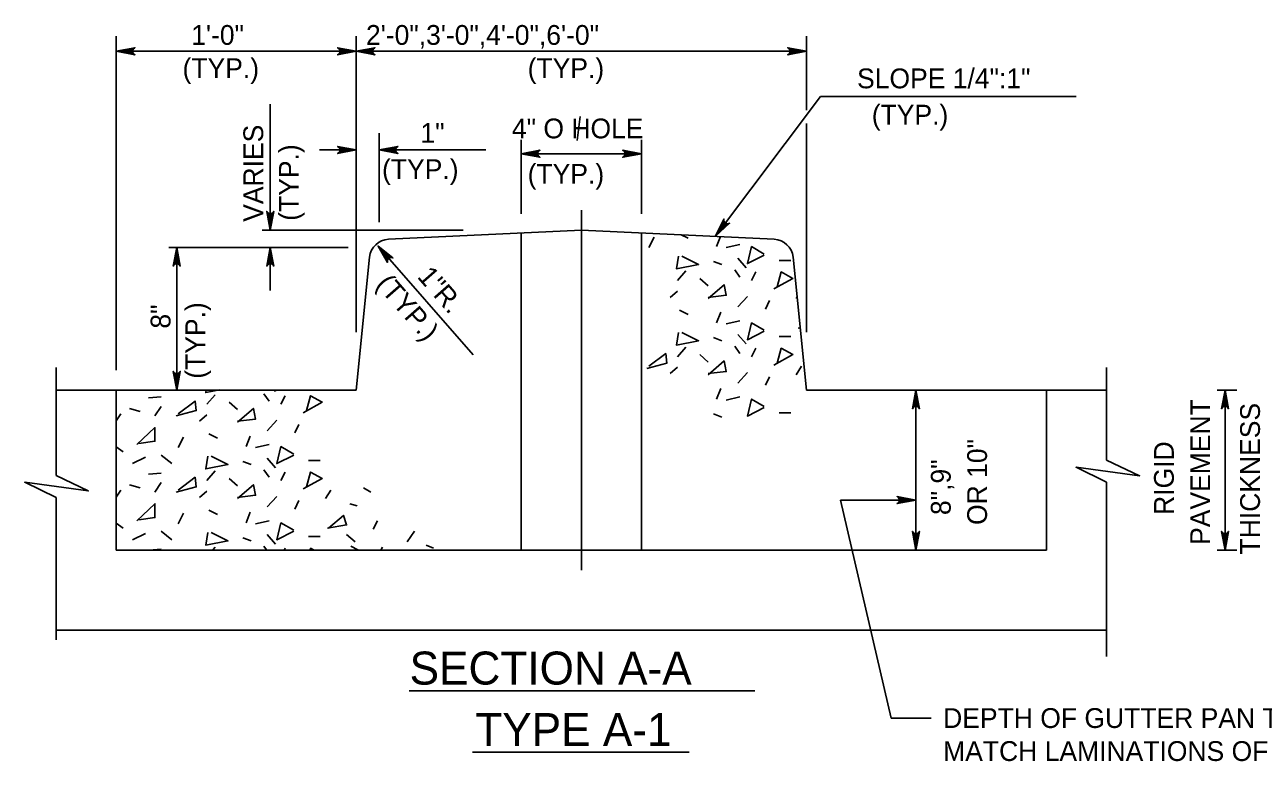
# Model space of a CAD drawing. Extents: x -49.1 to -41.9, y 44.5 to 54.6.
# Drawn here: x -49.016 to -45.264, y 52.405 to 54.637 of the extents above; entities that cross this region are included whole.
import ezdxf

# ---------------------------------------------------------------- set-up
doc = ezdxf.new("R2010")
doc.units = 0
for name, color, linetype in [('DETL-DIMS', 7, 'Continuous'), ('DETL-LINE', 7, 'Continuous'), ('DETL-NOTE', 7, 'Continuous'), ('DETL-PATT', 7, 'Continuous'), ('DETL-TITL', 7, 'Continuous')]:
    doc.layers.add(name, color=color, linetype=linetype)

msp = doc.modelspace()

# ---------------------------------------------------------------- linework, layer by layer
at = {"layer": 'DETL-DIMS'}
for p, q in [((-48.7387, 54.6017), (-48.7387, 53.5901)), ((-48.0114, 53.7047), (-48.0114, 54.6017)), ((-46.648, 54.6017), (-46.648, 54.3782)), ((-48.0114, 54.5565), (-48.7387, 54.5565)), ((-48.0114, 54.5565), (-46.648, 54.5565)), ((-46.9231, 53.9963), (-46.6054, 54.419)), ((-46.6054, 54.419), (-45.8303, 54.419)), ((-48.2719, 54.396), (-48.2719, 54.0143)), ((-46.648, 54.3375), (-46.648, 53.7047)), ((-47.9417, 54.0385), (-47.9417, 54.3077)), ((-47.5115, 54.2876), (-47.5115, 54.0639)), ((-47.1479, 54.2876), (-47.1479, 54.0639)), ((-48.1224, 54.2574), (-48.0114, 54.2574)), ((-47.9417, 54.2574), (-47.619, 54.2574)), ((-47.5115, 54.2457), (-47.1479, 54.2457)), ((-47.3297, 52.984), (-47.3297, 54.0749)), ((-47.6881, 54.0143), (-48.2961, 54.0143)), ((-48.0357, 53.9617), (-48.5797, 53.9617)), ((-48.5555, 53.5295), (-48.5555, 53.9617)), ((-48.2719, 53.9617), (-48.2719, 53.8316)), ((-47.9456, 53.9656), (-47.6575, 53.6361)), ((-46.3162, 53.0446), (-46.3162, 53.5295)), ((-45.4037, 53.5295), (-45.3441, 53.5295)), ((-45.3795, 53.0446), (-45.3795, 53.5295)), ((-46.3166, 53.1958), (-46.5443, 53.1958)), ((-46.5443, 53.1958), (-46.3909, 52.5354)), ((-45.4037, 53.0446), (-45.3441, 53.0446)), ((-46.3909, 52.5354), (-46.2697, 52.5354))]:
    msp.add_line(p, q, dxfattribs=at)
for points in [[(-48.7387, 54.5565), (-48.6822, 54.5671), (-48.6866, 54.5641), (-48.6888, 54.5603), (-48.6895, 54.5565), (-48.6888, 54.5527), (-48.6866, 54.5489), (-48.6822, 54.5459), (-48.7387, 54.5565), (-48.6866, 54.5489), (-48.6888, 54.5527), (-48.7387, 54.5565), (-48.6895, 54.5565), (-48.6888, 54.5603), (-48.7387, 54.5565), (-48.6866, 54.5641)], [(-48.0114, 54.5565), (-48.0679, 54.5671), (-48.0636, 54.5641), (-48.0613, 54.5603), (-48.0607, 54.5565), (-48.0613, 54.5527), (-48.0636, 54.5489), (-48.0679, 54.5459), (-48.0114, 54.5565), (-48.0636, 54.5489), (-48.0613, 54.5527), (-48.0114, 54.5565), (-48.0607, 54.5565), (-48.0613, 54.5603), (-48.0114, 54.5565), (-48.0636, 54.5641)], [(-48.0114, 54.5565), (-47.9549, 54.5671), (-47.9593, 54.5641), (-47.9615, 54.5603), (-47.9622, 54.5565), (-47.9615, 54.5527), (-47.9593, 54.5489), (-47.9549, 54.5459), (-48.0114, 54.5565), (-47.9593, 54.5489), (-47.9615, 54.5527), (-48.0114, 54.5565), (-47.9622, 54.5565), (-47.9615, 54.5603), (-48.0114, 54.5565), (-47.9593, 54.5641)], [(-46.648, 54.5565), (-46.7045, 54.5459), (-46.7001, 54.5489), (-46.6979, 54.5527), (-46.6972, 54.5565), (-46.6979, 54.5603), (-46.7001, 54.5641), (-46.7045, 54.5671), (-46.648, 54.5565), (-46.7001, 54.5641), (-46.6979, 54.5603), (-46.648, 54.5565), (-46.6972, 54.5565), (-46.6979, 54.5527), (-46.648, 54.5565), (-46.7001, 54.5489)], [(-48.0114, 54.2574), (-48.0679, 54.2468), (-48.0636, 54.2498), (-48.0613, 54.2536), (-48.0607, 54.2574), (-48.0613, 54.2612), (-48.0636, 54.265), (-48.0679, 54.268), (-48.0114, 54.2574), (-48.0636, 54.265), (-48.0613, 54.2612), (-48.0114, 54.2574), (-48.0607, 54.2574), (-48.0613, 54.2536), (-48.0114, 54.2574), (-48.0636, 54.2498)], [(-47.9417, 54.2574), (-47.8852, 54.268), (-47.8896, 54.265), (-47.8918, 54.2612), (-47.8925, 54.2574), (-47.8918, 54.2536), (-47.8896, 54.2498), (-47.8852, 54.2468), (-47.9417, 54.2574), (-47.8896, 54.2498), (-47.8918, 54.2536), (-47.9417, 54.2574), (-47.8925, 54.2574), (-47.8918, 54.2612), (-47.9417, 54.2574), (-47.8896, 54.265)], [(-47.5115, 54.2457), (-47.455, 54.2563), (-47.4594, 54.2533), (-47.4616, 54.2495), (-47.4623, 54.2457), (-47.4616, 54.2419), (-47.4594, 54.2381), (-47.455, 54.2351), (-47.5115, 54.2457), (-47.4594, 54.2381), (-47.4616, 54.2419), (-47.5115, 54.2457), (-47.4623, 54.2457), (-47.4616, 54.2495), (-47.5115, 54.2457), (-47.4594, 54.2533)], [(-47.5115, 54.2457), (-47.455, 54.2563), (-47.4594, 54.2533), (-47.4616, 54.2495), (-47.4623, 54.2457), (-47.4616, 54.2419), (-47.4594, 54.2381), (-47.455, 54.2351), (-47.5115, 54.2457), (-47.4594, 54.2381), (-47.4616, 54.2419), (-47.5115, 54.2457), (-47.4623, 54.2457), (-47.4616, 54.2495), (-47.5115, 54.2457), (-47.4594, 54.2533)], [(-47.1479, 54.2457), (-47.2044, 54.2351), (-47.2, 54.2381), (-47.1978, 54.2419), (-47.1971, 54.2457), (-47.1978, 54.2495), (-47.2, 54.2533), (-47.2044, 54.2563), (-47.1479, 54.2457), (-47.2, 54.2533), (-47.1978, 54.2495), (-47.1479, 54.2457), (-47.1971, 54.2457), (-47.1978, 54.2419), (-47.1479, 54.2457), (-47.2, 54.2381)], [(-48.2719, 54.0143), (-48.2825, 54.0708), (-48.2794, 54.0664), (-48.2756, 54.0642), (-48.2719, 54.0635), (-48.2681, 54.0642), (-48.2643, 54.0664), (-48.2613, 54.0708), (-48.2719, 54.0143), (-48.2643, 54.0664), (-48.2681, 54.0642), (-48.2719, 54.0143), (-48.2719, 54.0635), (-48.2756, 54.0642), (-48.2719, 54.0143), (-48.2794, 54.0664)], [(-46.9231, 53.9963), (-46.8976, 54.0478), (-46.8978, 54.0425), (-46.8961, 54.0384), (-46.8935, 54.0356), (-46.8901, 54.0339), (-46.8857, 54.0334), (-46.8807, 54.0351), (-46.9231, 53.9963), (-46.8857, 54.0334), (-46.8901, 54.0339), (-46.9231, 53.9963), (-46.8935, 54.0356), (-46.8961, 54.0384), (-46.9231, 53.9963), (-46.8978, 54.0425)], [(-48.5555, 53.9617), (-48.5449, 53.9052), (-48.5479, 53.9095), (-48.5517, 53.9118), (-48.5555, 53.9124), (-48.5593, 53.9118), (-48.563, 53.9095), (-48.5661, 53.9052), (-48.5555, 53.9617), (-48.563, 53.9095), (-48.5593, 53.9118), (-48.5555, 53.9617), (-48.5555, 53.9124), (-48.5517, 53.9118), (-48.5555, 53.9617), (-48.5479, 53.9095)], [(-48.5555, 53.9617), (-48.5449, 53.9052), (-48.5479, 53.9095), (-48.5517, 53.9118), (-48.5555, 53.9124), (-48.5593, 53.9118), (-48.563, 53.9095), (-48.5661, 53.9052), (-48.5555, 53.9617), (-48.563, 53.9095), (-48.5593, 53.9118), (-48.5555, 53.9617), (-48.5555, 53.9124), (-48.5517, 53.9118), (-48.5555, 53.9617), (-48.5479, 53.9095)], [(-48.2719, 53.9617), (-48.2613, 53.9052), (-48.2643, 53.9095), (-48.2681, 53.9118), (-48.2719, 53.9124), (-48.2756, 53.9118), (-48.2794, 53.9095), (-48.2825, 53.9052), (-48.2719, 53.9617), (-48.2794, 53.9095), (-48.2756, 53.9118), (-48.2719, 53.9617), (-48.2719, 53.9124), (-48.2681, 53.9118), (-48.2719, 53.9617), (-48.2643, 53.9095)], [(-47.9456, 53.9656), (-47.9005, 53.93), (-47.9056, 53.9313), (-47.9099, 53.9305), (-47.9132, 53.9285), (-47.9156, 53.9255), (-47.917, 53.9213), (-47.9164, 53.9161), (-47.9456, 53.9656), (-47.917, 53.9213), (-47.9156, 53.9255), (-47.9456, 53.9656), (-47.9132, 53.9285), (-47.9099, 53.9305), (-47.9456, 53.9656), (-47.9056, 53.9313)], [(-48.5555, 53.5295), (-48.5661, 53.586), (-48.563, 53.5816), (-48.5593, 53.5794), (-48.5555, 53.5787), (-48.5517, 53.5794), (-48.5479, 53.5816), (-48.5449, 53.586), (-48.5555, 53.5295), (-48.5479, 53.5816), (-48.5517, 53.5794), (-48.5555, 53.5295), (-48.5555, 53.5787), (-48.5593, 53.5794), (-48.5555, 53.5295), (-48.563, 53.5816)], [(-46.3162, 53.5295), (-46.3056, 53.473), (-46.3086, 53.4773), (-46.3124, 53.4796), (-46.3162, 53.4802), (-46.32, 53.4796), (-46.3238, 53.4773), (-46.3268, 53.473), (-46.3162, 53.5295), (-46.3238, 53.4773), (-46.32, 53.4796), (-46.3162, 53.5295), (-46.3162, 53.4802), (-46.3124, 53.4796), (-46.3162, 53.5295), (-46.3086, 53.4773)], [(-45.3795, 53.5295), (-45.3689, 53.473), (-45.3719, 53.4773), (-45.3757, 53.4796), (-45.3795, 53.4802), (-45.3832, 53.4796), (-45.387, 53.4773), (-45.3901, 53.473), (-45.3795, 53.5295), (-45.387, 53.4773), (-45.3832, 53.4796), (-45.3795, 53.5295), (-45.3795, 53.4802), (-45.3757, 53.4796), (-45.3795, 53.5295), (-45.3719, 53.4773)], [(-46.3166, 53.1958), (-46.3731, 53.1852), (-46.3687, 53.1882), (-46.3665, 53.192), (-46.3658, 53.1958), (-46.3665, 53.1996), (-46.3687, 53.2033), (-46.3731, 53.2064), (-46.3166, 53.1958), (-46.3687, 53.2033), (-46.3665, 53.1996), (-46.3166, 53.1958), (-46.3658, 53.1958), (-46.3665, 53.192), (-46.3166, 53.1958), (-46.3687, 53.1882)], [(-46.3162, 53.0446), (-46.3268, 53.1011), (-46.3238, 53.0968), (-46.32, 53.0945), (-46.3162, 53.0939), (-46.3124, 53.0945), (-46.3086, 53.0968), (-46.3056, 53.1011), (-46.3162, 53.0446), (-46.3086, 53.0968), (-46.3124, 53.0945), (-46.3162, 53.0446), (-46.3162, 53.0939), (-46.32, 53.0945), (-46.3162, 53.0446), (-46.3238, 53.0968)], [(-45.3795, 53.0446), (-45.3901, 53.1011), (-45.387, 53.0968), (-45.3832, 53.0945), (-45.3795, 53.0939), (-45.3757, 53.0945), (-45.3719, 53.0968), (-45.3689, 53.1011), (-45.3795, 53.0446), (-45.3719, 53.0968), (-45.3757, 53.0945), (-45.3795, 53.0446), (-45.3795, 53.0939), (-45.3832, 53.0945), (-45.3795, 53.0446), (-45.387, 53.0968)]]:
    msp.add_lwpolyline(points, dxfattribs=at)
at = {"layer": 'DETL-LINE'}
for p, q in [((-47.3297, 54.0143), (-47.9138, 53.9865)), ((-47.5115, 53.0446), (-47.5115, 54.0033)), ((-47.3297, 54.0143), (-46.7457, 53.9865)), ((-47.1479, 53.0446), (-47.1479, 54.0033)), ((-48.0114, 53.5295), (-47.9712, 53.932)), ((-46.648, 53.5295), (-46.6882, 53.932)), ((-48.9205, 53.5978), (-48.9205, 53.2701)), ((-45.7389, 53.5978), (-45.7389, 53.3173)), ((-48.9205, 53.5295), (-48.0114, 53.5295)), ((-48.7387, 53.5295), (-48.7387, 53.0446)), ((-46.648, 53.5295), (-45.7389, 53.5295)), ((-45.9207, 53.5295), (-45.9207, 53.0446)), ((-45.7389, 53.2508), (-45.7389, 52.7225)), ((-48.9205, 53.2035), (-48.9205, 52.7723)), ((-48.7387, 53.0446), (-45.9207, 53.0446)), ((-48.9205, 52.8022), (-45.7389, 52.8022))]:
    msp.add_line(p, q, dxfattribs=at)
for points in [[(-45.7389, 53.2508), (-45.8308, 53.2957), (-45.6385, 53.2696), (-45.7389, 53.3173)], [(-48.9205, 53.2035), (-49.0157, 53.2501), (-48.8234, 53.224), (-48.9205, 53.2701)]]:
    msp.add_lwpolyline(points, dxfattribs=at)
for centre, start, end in [((-47.9109, 53.926), 92.7268, 174.2895), ((-46.7486, 53.926), 5.7105, 87.2732)]:
    msp.add_arc(centre, 0.0606, start, end, dxfattribs=at)
at = {"layer": 'DETL-NOTE'}
msp.add_line((-47.3426, 54.2857), (-47.333, 54.3589), dxfattribs=at)
at = {"layer": 'DETL-PATT'}
for p, q in [((-47.1252, 53.9611), (-47.1091, 53.9932)), ((-47.0268, 54.0001), (-47.0065, 53.99)), ((-46.9078, 53.9944), (-46.9198, 53.9643)), ((-46.8492, 53.9707), (-46.8909, 53.9611)), ((-46.9294, 53.9194), (-46.9037, 53.9097)), ((-46.8556, 53.929), (-46.83, 53.9001)), ((-46.7305, 53.9226), (-46.6952, 53.9226)), ((-47.0385, 53.8616), (-47.0129, 53.8905)), ((-46.8652, 53.8937), (-46.8492, 53.8712)), ((-46.8011, 53.8873), (-46.8139, 53.8616)), ((-46.9711, 53.868), (-46.9455, 53.8456)), ((-47.061, 53.8102), (-47.0385, 53.8295)), ((-46.8267, 53.8135), (-46.8556, 53.7814)), ((-46.7594, 53.8006), (-46.7722, 53.775)), ((-46.6791, 53.807), (-46.6762, 53.8117)), ((-47.0321, 53.7717), (-47.0065, 53.7589)), ((-46.907, 53.7653), (-46.9198, 53.7332)), ((-46.8492, 53.7397), (-46.8909, 53.73)), ((-46.9294, 53.6883), (-46.9037, 53.6787)), ((-46.8556, 53.6979), (-46.83, 53.6691)), ((-46.7305, 53.6915), (-46.6952, 53.6915)), ((-47.0385, 53.6305), (-47.0129, 53.6594)), ((-46.8652, 53.6626), (-46.8492, 53.6402)), ((-46.8011, 53.6562), (-46.8139, 53.6305)), ((-46.9711, 53.637), (-46.9455, 53.6145)), ((-47.061, 53.5792), (-47.0385, 53.5985)), ((-46.8267, 53.5824), (-46.8556, 53.5503)), ((-46.6791, 53.576), (-46.6631, 53.6017)), ((-46.7594, 53.5696), (-46.7722, 53.5439)), ((-48.6408, 53.5057), (-48.6023, 53.5089)), ((-48.4643, 53.4865), (-48.4386, 53.5153)), ((-48.291, 53.5185), (-48.275, 53.4961)), ((-48.2604, 53.5302), (-48.2557, 53.525)), ((-48.2268, 53.5121), (-48.2396, 53.4865)), ((-46.907, 53.5343), (-46.9198, 53.5022)), ((-46.8492, 53.5086), (-46.8909, 53.499)), ((-48.6986, 53.4736), (-48.6665, 53.464)), ((-48.6215, 53.4511), (-48.6023, 53.48)), ((-48.3969, 53.4929), (-48.3712, 53.4704)), ((-46.7305, 53.4605), (-46.6952, 53.4605)), ((-48.7242, 53.4576), (-48.7387, 53.4359)), ((-48.4868, 53.4351), (-48.4643, 53.4544)), ((-48.2525, 53.4383), (-48.2814, 53.4062)), ((-48.1851, 53.4255), (-48.1979, 53.3998)), ((-46.9294, 53.4572), (-46.9037, 53.4476)), ((-48.5509, 53.3549), (-48.5349, 53.387)), ((-48.4579, 53.3966), (-48.4322, 53.3838)), ((-48.3327, 53.3902), (-48.3455, 53.3581)), ((-48.7387, 53.357), (-48.7178, 53.342)), ((-48.275, 53.3645), (-48.3167, 53.3549)), ((-48.6504, 53.326), (-48.6889, 53.3068)), ((-48.6023, 53.3324), (-48.5702, 53.3068)), ((-48.3552, 53.3132), (-48.3295, 53.3035)), ((-48.2814, 53.3228), (-48.2557, 53.2939)), ((-48.1562, 53.3164), (-48.1209, 53.3164)), ((-48.6408, 53.2746), (-48.6023, 53.2779)), ((-48.4643, 53.2554), (-48.4386, 53.2843)), ((-48.291, 53.2875), (-48.275, 53.265)), ((-48.2268, 53.2811), (-48.2396, 53.2554)), ((-48.6986, 53.2426), (-48.6665, 53.2329)), ((-48.6215, 53.2201), (-48.6023, 53.249)), ((-48.3969, 53.2618), (-48.3712, 53.2394)), ((-48.7242, 53.2265), (-48.7387, 53.2048)), ((-48.4868, 53.204), (-48.4643, 53.2233)), ((-48.2525, 53.2072), (-48.2814, 53.1752)), ((-48.1049, 53.2008), (-48.0888, 53.2265)), ((-47.9893, 53.2329), (-47.9669, 53.2201)), ((-48.4579, 53.1655), (-48.4322, 53.1527)), ((-48.1851, 53.1944), (-48.1979, 53.1687)), ((-48.031, 53.1848), (-48.0086, 53.1784)), ((-48.7387, 53.1259), (-48.7178, 53.111)), ((-48.5509, 53.1238), (-48.5349, 53.1559)), ((-48.3327, 53.1591), (-48.3455, 53.127)), ((-48.275, 53.1334), (-48.3167, 53.1238)), ((-47.9605, 53.1078), (-47.9476, 53.1334)), ((-48.6504, 53.0949), (-48.6889, 53.0757)), ((-48.6023, 53.1014), (-48.5702, 53.0757)), ((-48.2814, 53.0917), (-48.2557, 53.0629)), ((-48.1562, 53.0853), (-48.1209, 53.0853)), ((-48.0407, 53.0917), (-48.015, 53.0693)), ((-47.8353, 53.1014), (-47.8577, 53.0693)), ((-48.4459, 53.045), (-48.4386, 53.0532)), ((-48.3552, 53.0821), (-48.3295, 53.0725)), ((-48.291, 53.0564), (-48.283, 53.0453)), ((-48.2268, 53.05), (-48.2291, 53.0453)), ((-48.0278, 53.0564), (-48.0063, 53.0457)), ((-47.9358, 53.0458), (-47.9316, 53.0532)), ((-47.8, 53.0596), (-47.7775, 53.05)), ((-48.6266, 53.0448), (-48.6023, 53.0468)), ((-48.6266, 53.0448), (-48.6266, 53.0448)), ((-48.6266, 53.0448), (-48.6266, 53.0448)), ((-48.6266, 53.0448), (-48.6266, 53.0448))]:
    msp.add_line(p, q, dxfattribs=at)
for points in [[(-46.7754, 53.9386), (-46.8267, 53.913), (-46.8139, 53.9643), (-46.7754, 53.9418)], [(-47.0353, 53.9354), (-47.0418, 53.8969), (-46.9744, 53.9097), (-47.0257, 53.9354)], [(-46.7465, 53.8359), (-46.6887, 53.868), (-46.724, 53.8873), (-46.7369, 53.8424)], [(-46.9455, 53.8102), (-46.8909, 53.8167), (-46.8973, 53.8488), (-46.9455, 53.807)], [(-46.7754, 53.7076), (-46.8267, 53.6819), (-46.8139, 53.7332), (-46.7754, 53.7108)], [(-47.0353, 53.7044), (-47.0418, 53.6659), (-46.9744, 53.6787), (-47.0257, 53.7044)], [(-46.6727, 53.7172), (-46.6669, 53.7182)], [(-46.667, 53.7194), (-46.6695, 53.7172)], [(-46.7465, 53.6049), (-46.6887, 53.637), (-46.724, 53.6562), (-46.7369, 53.6113)], [(-47.1316, 53.5953), (-47.0706, 53.6113), (-47.0739, 53.6402), (-47.1252, 53.6017)], [(-46.9455, 53.5792), (-46.8909, 53.5856), (-46.8973, 53.6177), (-46.9455, 53.576)], [(-48.4661, 53.5299), (-48.4675, 53.5217), (-48.4243, 53.53)], [(-48.4243, 53.53), (-48.4243, 53.53)], [(-48.4243, 53.53), (-48.4243, 53.53)], [(-48.4243, 53.53), (-48.4243, 53.53)], [(-48.4243, 53.53), (-48.4243, 53.53)], [(-48.4243, 53.53), (-48.4243, 53.53)], [(-48.4243, 53.53), (-48.4243, 53.53)], [(-48.4243, 53.53), (-48.4243, 53.53)], [(-48.4243, 53.53), (-48.4243, 53.53)], [(-48.4243, 53.53), (-48.4243, 53.53)], [(-48.4243, 53.53), (-48.4243, 53.53)], [(-48.4243, 53.53), (-48.4243, 53.53)], [(-48.4243, 53.53), (-48.4243, 53.53)], [(-48.4243, 53.53), (-48.4243, 53.53)], [(-48.4243, 53.53), (-48.4243, 53.53)], [(-48.4243, 53.53), (-48.4243, 53.53)], [(-48.4243, 53.53), (-48.4243, 53.53)], [(-48.4243, 53.53), (-48.4243, 53.53)], [(-48.4243, 53.53), (-48.4243, 53.53)], [(-48.4243, 53.53), (-48.4243, 53.53)], [(-48.1722, 53.4608), (-48.1145, 53.4929), (-48.1498, 53.5121), (-48.1626, 53.4672)], [(-46.7754, 53.4765), (-46.8267, 53.4508), (-46.8139, 53.5022), (-46.7754, 53.4797)], [(-48.5574, 53.4511), (-48.4964, 53.4672), (-48.4996, 53.4961), (-48.5509, 53.4576)], [(-48.3712, 53.4351), (-48.3167, 53.4415), (-48.3231, 53.4736), (-48.3712, 53.4319)], [(-48.6697, 53.3677), (-48.6215, 53.3741), (-48.6215, 53.4159), (-48.6761, 53.3645)], [(-48.2011, 53.3324), (-48.2525, 53.3068), (-48.2396, 53.3581), (-48.2011, 53.3356)], [(-48.4611, 53.3292), (-48.4675, 53.2907), (-48.4001, 53.3035), (-48.4515, 53.3292)], [(-48.1722, 53.2297), (-48.1145, 53.2618), (-48.1498, 53.2811), (-48.1626, 53.2361)], [(-48.5574, 53.2201), (-48.4964, 53.2361), (-48.4996, 53.265), (-48.5509, 53.2265)], [(-48.3712, 53.204), (-48.3167, 53.2105), (-48.3231, 53.2426), (-48.3712, 53.2008)], [(-48.6697, 53.1366), (-48.6215, 53.1431), (-48.6215, 53.1848), (-48.6761, 53.1334)], [(-48.2011, 53.1014), (-48.2525, 53.0757), (-48.2396, 53.127), (-48.2011, 53.1046)], [(-48.0984, 53.111), (-48.0407, 53.1206), (-48.0503, 53.1495), (-48.0952, 53.111)], [(-48.4611, 53.0981), (-48.4675, 53.0596), (-48.4001, 53.0725), (-48.4515, 53.0981)], [(-48.1415, 53.0455), (-48.1498, 53.05), (-48.1511, 53.0455)]]:
    msp.add_lwpolyline(points, dxfattribs=at)
at = {"layer": 'DETL-TITL'}
for p, q in [((-47.8513, 52.6183), (-46.8043, 52.6183)), ((-47.6596, 52.432), (-47.0034, 52.432))]:
    msp.add_line(p, q, dxfattribs=at)

# ---------------------------------------------------------------- texts
at = {"layer": 'DETL-NOTE'}
for s, p in [('1\'-0"', (-48.5114, 54.5757)), ('2\'-0",3\'-0",4\'-0",6\'-0"', (-47.982, 54.5757)), ('(TYP.)', (-48.5377, 54.475)), ('(TYP.)', (-47.4923, 54.475)), ('SLOPE 1/4":1"', (-46.4945, 54.444)), ('  (TYP.) ', (-46.4945, 54.334)), ('1"', (-47.8171, 54.279)), ('4" O HOLE', (-47.54, 54.2923)), ('(TYP.)', (-47.9334, 54.169)), ('(TYP.)', (-47.4923, 54.1546)), ('DEPTH OF GUTTER PAN TO', (-46.2337, 52.5054)), ('MATCH LAMINATIONS OF', (-46.2337, 52.4054))]:
    msp.add_text(s, height=0.06, dxfattribs=at).set_placement(p)
for s, rotation, p in [('VARIES', 90, (-48.2934, 54.0394)), ('(TYP.)', 90, (-48.1855, 54.0425)), ('(TYP.)', 311.1703, (-47.9544, 53.8478)), ('1"R.', 311.1703, (-47.8292, 53.8718)), ('8"', 90, (-48.5743, 53.7157)), ('(TYP.)', 90, (-48.4691, 53.5638)), ('PAVEMENT', 90, (-45.4249, 53.0603)), ('THICKNESS', 90, (-45.274, 53.0313)), ('OR 10"', 90, (-46.1008, 53.1207)), ('RIGID', 90, (-45.5349, 53.1511)), ('8",9"', 90, (-46.2108, 53.1507))]:
    msp.add_text(s, height=0.06, rotation=rotation, dxfattribs=at).set_placement(p)
at = {"layer": 'DETL-TITL'}
for s, p in [('SECTION A-A', (-47.8499, 52.6369)), ('TYPE A-1', (-47.6509, 52.4506))]:
    msp.add_text(s, height=0.1, dxfattribs=at).set_placement(p)

doc.saveas('drawing.dxf')
